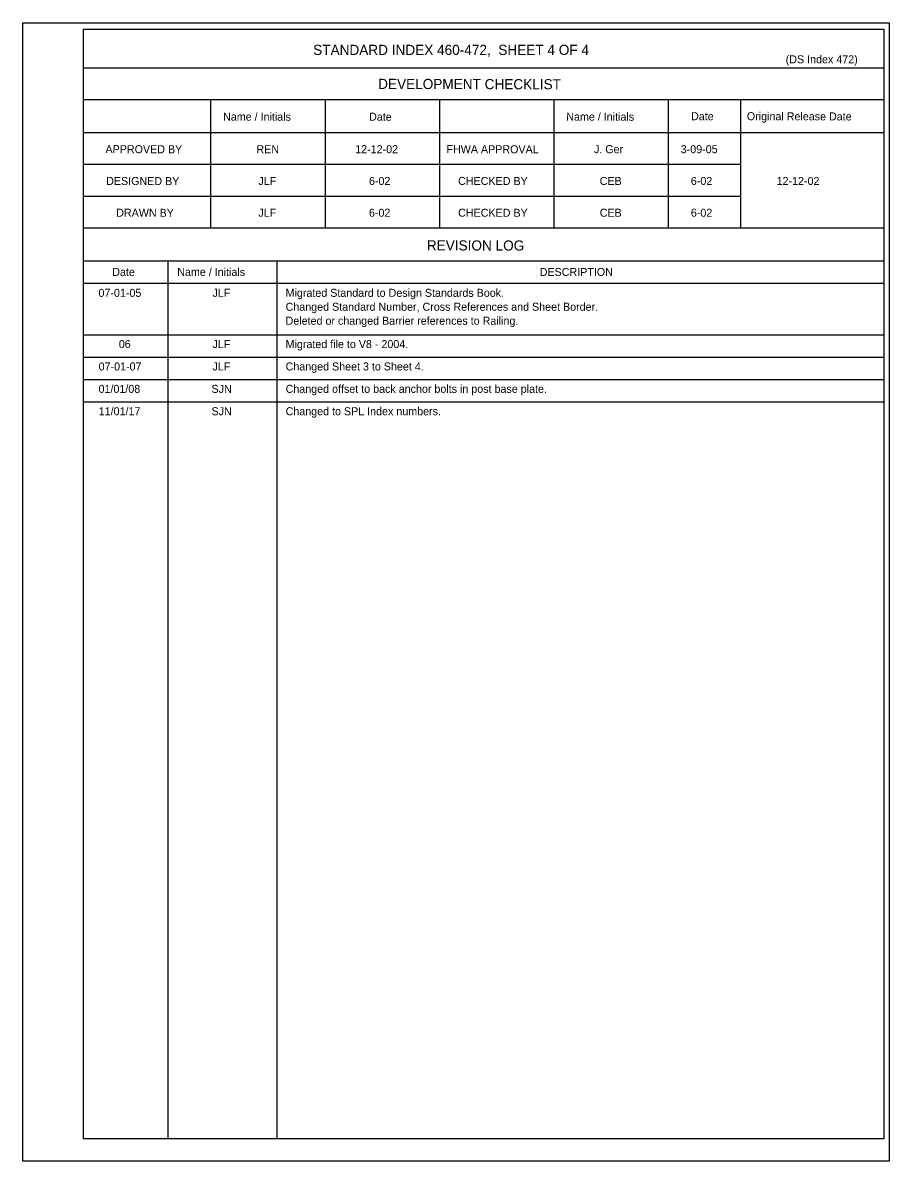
# Model space of a CAD drawing. Extents: x 21587 to 21656.3, y 56114 to 56157.2.
# Drawn here: x 21634.51 to 21656.33, y 56124.78 to 56153.45 of the extents above; entities that cross this region are included whole.
import ezdxf

# ---------------------------------------------------------------- set-up
doc = ezdxf.new("R2010")
doc.units = 0
for name, color, linetype in [('Border', 7, 'Continuous'), ('PlotBorder_dp', 7, 'Continuous'), ('SheetBorder_dp', 7, 'Continuous')]:
    doc.layers.add(name, color=color, linetype=linetype)

msp = doc.modelspace()

# ---------------------------------------------------------------- linework, layer by layer
at = {"layer": 'Border'}
for p, q in [((21656.191, 56152.307), (21636.044, 56152.307)), ((21656.191, 56151.507), (21636.044, 56151.507)), ((21639.244, 56151.507), (21639.244, 56148.279)), ((21642.124, 56151.507), (21642.124, 56148.279)), ((21645.004, 56151.507), (21645.004, 56148.279)), ((21647.884, 56151.507), (21647.884, 56148.279)), ((21650.764, 56151.507), (21650.764, 56148.279)), ((21652.579, 56151.507), (21652.579, 56148.279)), ((21656.191, 56150.679), (21636.044, 56150.679)), ((21652.579, 56149.879), (21636.044, 56149.879)), ((21652.579, 56149.079), (21636.044, 56149.079)), ((21656.191, 56148.279), (21636.044, 56148.279)), ((21656.191, 56147.451), (21636.044, 56147.451)), ((21638.165, 56147.451), (21638.165, 56125.345)), ((21640.907, 56147.451), (21640.907, 56125.345)), ((21656.191, 56146.887), (21636.044, 56146.887))]:
    msp.add_line(p, q, dxfattribs=at)
msp.add_lwpolyline([(21636.045, 56153.287), (21656.191, 56153.287), (21656.191, 56125.345), (21636.045, 56125.345)], close=True, dxfattribs=at)
at = {"layer": 'PlotBorder_dp'}
for p, q in [((21636.045, 56145.596), (21656.191, 56145.596)), ((21636.045, 56145.033), (21656.191, 56145.033)), ((21636.045, 56144.469), (21656.191, 56144.469)), ((21636.045, 56143.905), (21656.191, 56143.905)), ((21634.514, 56124.783), (21634.514, 56124.783))]:
    msp.add_line(p, q, dxfattribs=at)
msp.add_lwpolyline([(21634.514, 56153.45), (21656.327, 56153.45), (21656.327, 56124.783), (21634.514, 56124.783)], close=True, dxfattribs=at)

# ---------------------------------------------------------------- texts
at = {"layer": 'SheetBorder_dp'}
for s, height, p in [('STANDARD INDEX 460-472,  SHEET 4 OF 4', 0.256, (21641.825, 56152.639)), ('(DS Index 472)', 0.2016, (21653.721, 56152.429)), ('REN', 0.2016, (21640.396, 56150.166)), ('12-12-02', 0.2016, (21642.883, 56150.166)), ('J. Ger', 0.2016, (21648.894, 56150.166)), ('3-09-05', 0.2016, (21651.078, 56150.166)), ('JLF', 0.2016, (21640.444, 56149.366)), ('6-02', 0.2016, (21643.229, 56149.366)), ('CEB', 0.2016, (21649.039, 56149.366)), ('6-02', 0.2016, (21651.333, 56149.366)), ('12-12-02', 0.2016, (21653.492, 56149.366)), ('JLF', 0.2016, (21640.444, 56148.566)), ('6-02', 0.2016, (21643.229, 56148.566)), ('CEB', 0.2016, (21649.039, 56148.566)), ('6-02', 0.2016, (21651.333, 56148.566)), ('DESCRIPTION', 0.2016, (21647.528, 56147.074)), ('07-01-05', 0.2016, (21636.42, 56146.549)), ('JLF', 0.2016, (21639.291, 56146.549)), ('Migrated Standard to Design Standards Book.', 0.2016, (21641.131, 56146.549)), ('Changed Standard Number, Cross References and Sheet Border.', 0.2016, (21641.131, 56146.198)), ('Deleted or changed Barrier references to Railing.', 0.2016, (21641.131, 56145.846)), ('06', 0.2016, (21636.932, 56145.258)), ('JLF', 0.2016, (21639.291, 56145.258)), ('Migrated file to V8 - 2004.', 0.2016, (21641.131, 56145.258)), ('07-01-07', 0.2016, (21636.424, 56144.695)), ('JLF', 0.2016, (21639.291, 56144.695)), ('Changed Sheet 3 to Sheet 4.', 0.2016, (21641.131, 56144.695)), ('01/01/08', 0.2016, (21636.422, 56144.131)), ('SJN', 0.2016, (21639.266, 56144.131)), ('Changed offset to back anchor bolts in post base plate.', 0.2016, (21641.131, 56144.131)), ('11/01/17', 0.2016, (21636.426, 56143.567)), ('SJN', 0.2016, (21639.266, 56143.567)), ('Changed to SPL Index numbers.', 0.2016, (21641.131, 56143.567))]:
    msp.add_text(s, height=height, dxfattribs=at).set_placement(p)
for s, height, p in [('DEVELOPMENT CHECKLIST', 0.256, (21643.46, 56151.783)), ('Name / Initials', 0.2016, (21639.557, 56150.986)), ('Date', 0.2016, (21643.232, 56150.984)), ('Name / Initials', 0.2016, (21648.197, 56150.986)), ('Date', 0.2016, (21651.337, 56150.996)), ('Original Release Date', 0.2016, (21652.743, 56150.996)), ('APPROVED BY', 0.2016, (21636.596, 56150.167)), ('FHWA APPROVAL', 0.2016, (21645.18, 56150.167)), ('DESIGNED BY', 0.2016, (21636.613, 56149.366)), ('CHECKED BY', 0.2016, (21645.474, 56149.367)), ('DRAWN BY', 0.2016, (21636.866, 56148.566)), ('CHECKED BY', 0.2016, (21645.474, 56148.567)), ('REVISION LOG', 0.256, (21644.686, 56147.718)), ('Name / Initials', 0.2016, (21638.403, 56147.076)), ('Date', 0.2016, (21636.767, 56147.075))]:
    msp.add_text(s, height=height, rotation=359.8756, dxfattribs=at).set_placement(p)

doc.saveas('drawing.dxf')
